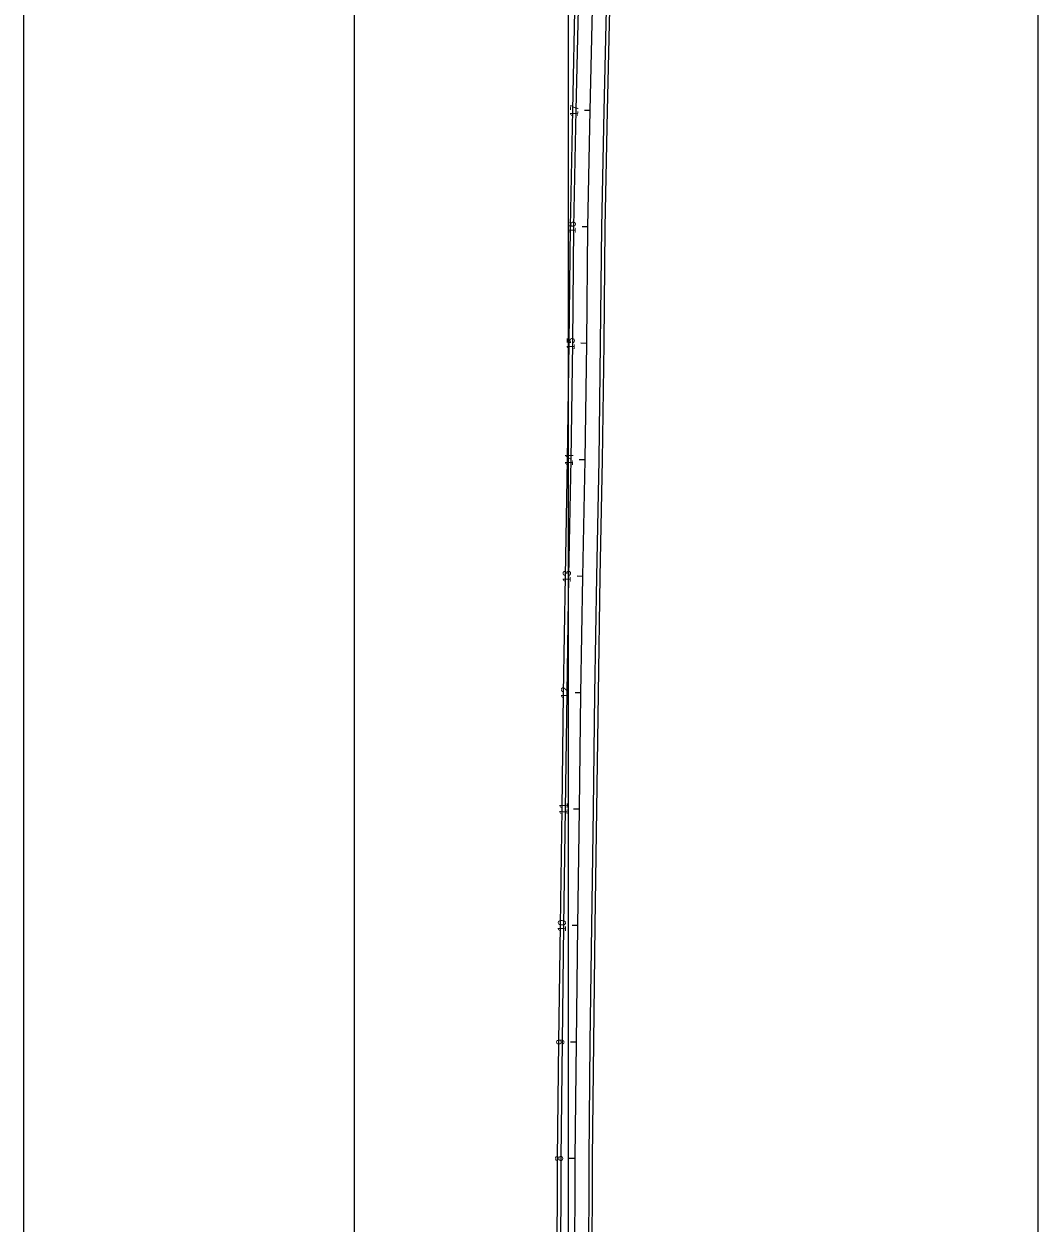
# Model space of a CAD drawing. Extents: x 2318076 to 2324211, y 613525 to 630327.
# Drawn here: x 2318413 to 2319284, y 615680 to 616710 of the extents above; entities that cross this region are included whole.
import ezdxf

# ---------------------------------------------------------------- set-up
doc = ezdxf.new("R2010")
doc.units = 0
for name, color, linetype in [('GE_P_CL_50', 7, 'Continuous'), ('PV_P_EOP', 7, 'Continuous'), ('PV_P_Shoulder', 7, 'Continuous'), ('SC_Scratch3', 7, 'Continuous')]:
    doc.layers.add(name, color=color, linetype=linetype)

msp = doc.modelspace()

# ---------------------------------------------------------------- linework, layer by layer
at = {"layer": 'GE_P_CL_50'}
for p, q in [((2318899.2, 616635.4), (2318894.2, 616635.5)), ((2318897.2, 616535.4), (2318892.2, 616535.5)), ((2318896.2, 616435.4), (2318891.2, 616435.5)), ((2318894.8, 616335.4), (2318889.8, 616335.5)), ((2318892.9, 616235.4), (2318887.9, 616235.5)), ((2318891.3, 616135.5), (2318886.3, 616135.5)), ((2318890, 616035.5), (2318885, 616035.5)), ((2318888.6, 615935.5), (2318883.6, 615935.6)), ((2318887.3, 615835.5), (2318882.3, 615835.5)), ((2318886.2, 615735.5), (2318881.2, 615735.6))]:
    msp.add_line(p, q, dxfattribs=at)
msp.add_lwpolyline([(2318885.9, 615635.5), (2318886.2, 615735.5), (2318887.3, 615835.5), (2318888.6, 615935.5), (2318890, 616035.5), (2318891.3, 616134.6), (2318892.9, 616235.4), (2318894.8, 616335.4), (2318896.2, 616435.4), (2318897.2, 616535.4), (2318899.2, 616635.4), (2318901.4, 616735.4), (2318903.1, 616835.4), (2318904.5, 616935.3), (2318906.2, 617035.3), (2318907.6, 617135.3), (2318909.8, 617235.3), (2318911.9, 617335.3), (2318913.9, 617435.2), (2318914.6, 617477.3), (2318915.8, 617533.4), (2318918, 617635.2), (2318920.2, 617734.2), (2318922.5, 617835.2)], dxfattribs=at)
at = {"layer": 'PV_P_EOP'}
for points in [[(2318873.9, 615635.6), (2318874.2, 615735.6), (2318875.3, 615835.6), (2318876.6, 615935.6), (2318878, 616035.6), (2318879.3, 616134.8), (2318880.9, 616235.7), (2318882.8, 616335.6), (2318884.2, 616435.6), (2318885.2, 616535.6), (2318887.2, 616635.6), (2318889.4, 616735.6), (2318891.1, 616835.5), (2318892.5, 616935.5), (2318894.2, 617035.5), (2318895.6, 617135.5), (2318897.8, 617235.5), (2318899.9, 617335.5), (2318902, 617435.5), (2318902.6, 617477.5), (2318903.8, 617533.7), (2318906, 617635.5), (2318908.2, 617734.5), (2318910.5, 617835.4)], [(2318897.9, 615635.4), (2318898.2, 615735.4), (2318899.3, 615835.3), (2318900.6, 615935.3), (2318902, 616035.3), (2318903.3, 616134.4), (2318904.8, 616235.2), (2318906.8, 616335.2), (2318908.2, 616435.3), (2318909.2, 616535.2), (2318911.2, 616635.1), (2318913.4, 616735.1), (2318915.1, 616835.2), (2318916.5, 616935.2), (2318918.2, 617035.1), (2318919.6, 617135.1), (2318921.8, 617235), (2318923.9, 617335), (2318925.9, 617435), (2318926.6, 617477), (2318927.8, 617533.2), (2318930, 617634.9), (2318932.2, 617733.9), (2318934.5, 617834.9)]]:
    msp.add_lwpolyline(points, dxfattribs=at)
at = {"layer": 'PV_P_Shoulder'}
for points in [[(2318870.9, 615635.6), (2318871.2, 615735.6), (2318872.3, 615835.7), (2318873.6, 615935.7), (2318875, 616035.7), (2318876.3, 616134.8), (2318877.9, 616235.7), (2318879.8, 616335.7), (2318881.2, 616435.6), (2318882.2, 616535.6), (2318884.2, 616635.7), (2318886.4, 616735.7), (2318888.1, 616835.6), (2318889.5, 616935.6), (2318891.2, 617035.6), (2318892.6, 617135.6), (2318894.8, 617235.6), (2318896.9, 617335.6), (2318899, 617435.5), (2318899.6, 617477.6), (2318900.8, 617533.7), (2318903, 617635.5), (2318905.2, 617734.5), (2318907.5, 617835.5)], [(2318900.9, 615635.4), (2318901.2, 615735.4), (2318902.3, 615835.3), (2318903.6, 615935.3), (2318905, 616035.3), (2318906.3, 616134.4), (2318907.8, 616235.2), (2318909.8, 616335.2), (2318911.2, 616435.2), (2318912.2, 616535.2), (2318914.2, 616635.1), (2318916.4, 616735.1), (2318918.1, 616835.1), (2318919.5, 616935.1), (2318921.2, 617035.1), (2318922.6, 617135), (2318924.8, 617235), (2318926.9, 617335), (2318928.9, 617435), (2318929.6, 617477), (2318930.8, 617533.1), (2318933, 617634.9), (2318935.2, 617733.9), (2318937.5, 617834.8)]]:
    msp.add_lwpolyline(points, dxfattribs=at)
at = {"layer": 'SC_Scratch3'}
for p, q in [((2318412.8, 614778.4), (2318412.8, 630327.2)), ((2318696.7, 614778.4), (2318696.7, 630327.2)), ((2318880.5, 614778.4), (2318880.5, 630327.2)), ((2319283.9, 614778.4), (2319283.9, 630327.2))]:
    msp.add_line(p, q, dxfattribs=at)

# ---------------------------------------------------------------- texts
at = {"layer": 'GE_P_CL_50'}
for s, rotation, p in [('17', 88.5663, (2318888.8, 616629.9)), ('16', 89.2594, (2318886.8, 616529.9)), ('15', 89.5566, (2318885.9, 616430)), ('14', 88.6506, (2318884.4, 616330.3)), ('13', 89.0608, (2318882.5, 616230.2)), ('12', 89.4127, (2318881, 616130.2)), ('11', 89.099, (2318879.6, 616030.5)), ('10', 89.0912, (2318878.3, 615930.1)), ('9', 89.5258, (2318877, 615832.9)), ('8', 89.3066, (2318875.9, 615732.9))]:
    msp.add_text(s, height=7, rotation=rotation, dxfattribs=at).set_placement(p)

doc.saveas('drawing.dxf')
